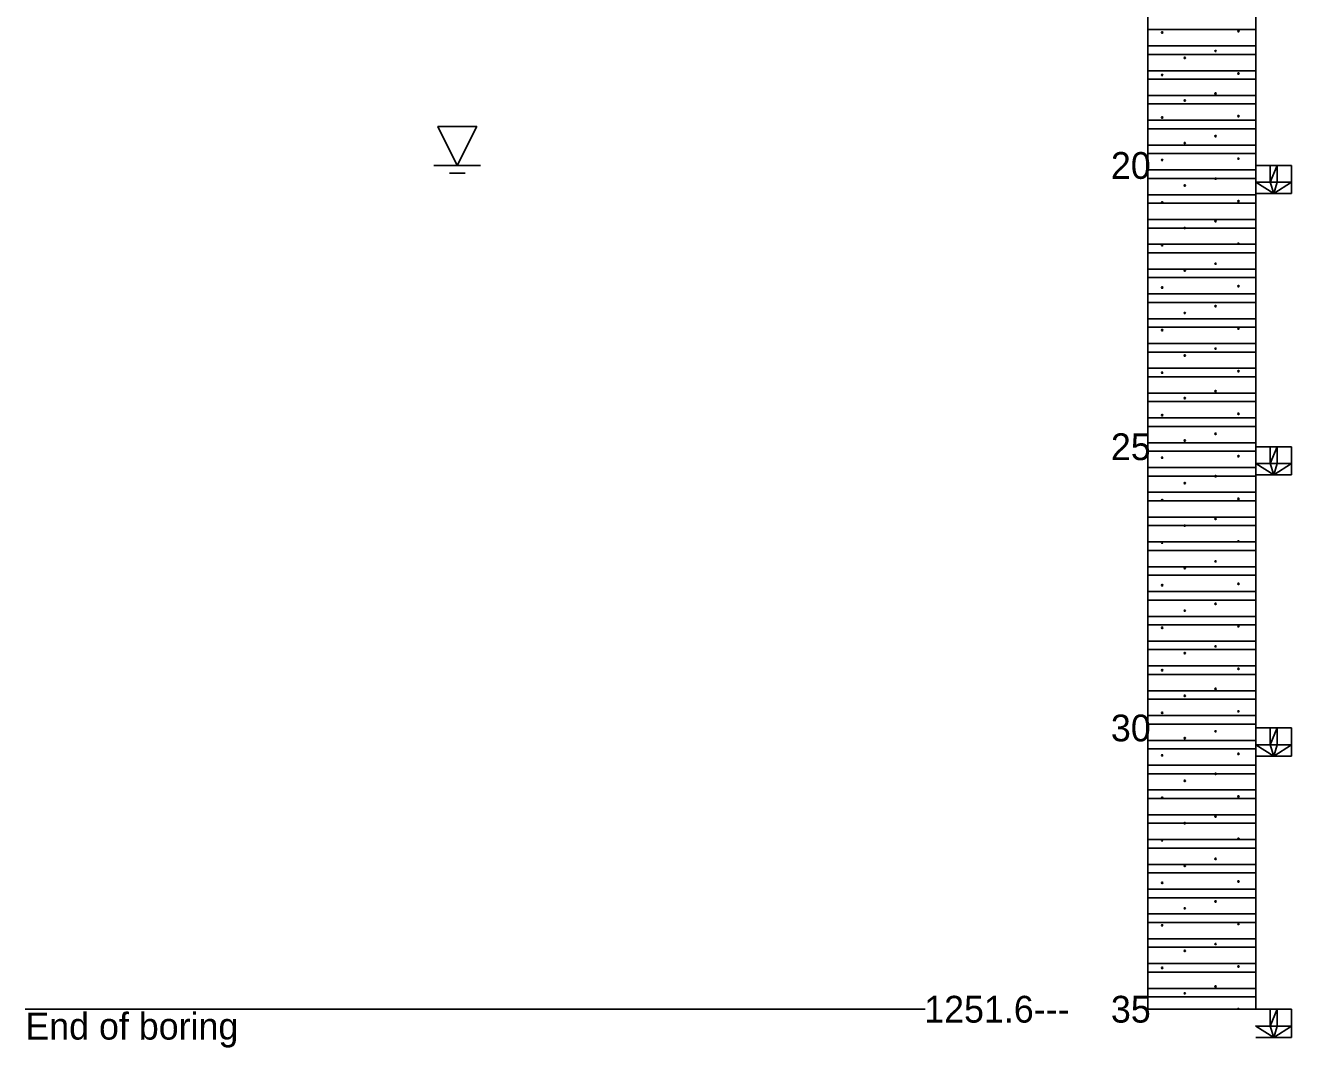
# Model space of a CAD drawing. Extents: x -2 to 138, y 24 to 58.
# Drawn here: x 54.71 to 60.57, y 39.72 to 44.45 of the extents above; entities that cross this region are included whole.
import ezdxf

# ---------------------------------------------------------------- set-up
doc = ezdxf.new("R2010")
doc.units = 0
doc.layers.add('Text', color=7, linetype='Continuous')

# ---------------------------------------------------------------- blocks, each defined once
blk = doc.blocks.new('DGRFC_WTLEV1_1')
for points in [[(0, 0), (0.00417, 0.00833), (-0.00417, 0.00833), (0, 0)], [(-0.005, 0), (0.005, 0)], [(-0.00167, -0.00167), (0.00167, -0.00167)]]:
    blk.add_lwpolyline(points)

msp = doc.modelspace()

# ---------------------------------------------------------------- linework, layer by layer
for points in [[(59.9039, 49.0098), (59.9039, 39.8952)], [(60.4039, 49.0098), (60.4039, 39.8952)], [(59.9039, 44.4306), (60.4039, 44.4306)], [(59.9743, 44.4172), (59.9726, 44.42), (59.9693, 44.42), (59.9677, 44.4172), (59.9693, 44.4143), (59.9726, 44.4143), (59.9743, 44.4172)], [(60.327, 44.4237), (60.3254, 44.4266), (60.3221, 44.4266), (60.3205, 44.4237), (60.3221, 44.4209), (60.3254, 44.4209), (60.327, 44.4237)], [(59.9039, 44.3551), (60.4039, 44.3551)], [(60.2215, 44.3312), (60.2199, 44.334), (60.2166, 44.334), (60.215, 44.3312), (60.2166, 44.3284), (60.2199, 44.3284), (60.2215, 44.3312)], [(59.9039, 44.3158), (60.4039, 44.3158)], [(60.0789, 44.2993), (60.0773, 44.3022), (60.074, 44.3022), (60.0724, 44.2993), (60.074, 44.2965), (60.0773, 44.2965), (60.0789, 44.2993)], [(59.9039, 44.2403), (60.4039, 44.2403)], [(59.9743, 44.2203), (59.9726, 44.2232), (59.9693, 44.2232), (59.9677, 44.2203), (59.9693, 44.2175), (59.9726, 44.2175), (59.9743, 44.2203)], [(60.327, 44.2268), (60.3254, 44.2297), (60.3221, 44.2297), (60.3205, 44.2268), (60.3221, 44.224), (60.3254, 44.224), (60.327, 44.2268)], [(59.9039, 44.2009), (60.4039, 44.2009)], [(59.9039, 44.1255), (60.4039, 44.1255)], [(60.0789, 44.1024), (60.0773, 44.1053), (60.074, 44.1053), (60.0724, 44.1025), (60.074, 44.0996), (60.0773, 44.0996), (60.0789, 44.1024)], [(60.2215, 44.1343), (60.2199, 44.1371), (60.2166, 44.1371), (60.215, 44.1343), (60.2166, 44.1315), (60.2199, 44.1315), (60.2215, 44.1343)], [(59.9039, 44.0861), (60.4039, 44.0861)], [(60.327, 44.03), (60.3254, 44.0329), (60.3221, 44.0329), (60.3205, 44.03), (60.3221, 44.0272), (60.3254, 44.0272), (60.327, 44.03)], [(59.9039, 44.0106), (60.4039, 44.0106)], [(59.9743, 44.0235), (59.9726, 44.0263), (59.9693, 44.0263), (59.9677, 44.0235), (59.9693, 44.0206), (59.9726, 44.0206), (59.9743, 44.0235)], [(59.9039, 43.9713), (60.4039, 43.9713)], [(60.2215, 43.9375), (60.2199, 43.9403), (60.2166, 43.9403), (60.215, 43.9375), (60.2166, 43.9347), (60.2199, 43.9347), (60.2215, 43.9375)], [(59.9039, 43.8958), (60.4039, 43.8958)], [(60.0789, 43.9056), (60.0773, 43.9085), (60.074, 43.9085), (60.0724, 43.9056), (60.074, 43.9028), (60.0773, 43.9028), (60.0789, 43.9056)], [(59.9039, 43.8564), (60.4039, 43.8564)], [(59.9743, 43.8266), (59.9726, 43.8295), (59.9693, 43.8295), (59.9677, 43.8266), (59.9693, 43.8238), (59.9726, 43.8238), (59.9743, 43.8266)], [(60.327, 43.8331), (60.3254, 43.836), (60.3221, 43.836), (60.3205, 43.8331), (60.3221, 43.8303), (60.3254, 43.8303), (60.327, 43.8331)], [(60.4039, 43.8015), (60.5705, 43.8015)], [(60.5705, 43.6713), (60.5705, 43.8015)], [(59.9039, 43.781), (60.4039, 43.781)], [(59.9039, 43.7416), (60.4039, 43.7416)], [(60.2215, 43.7406), (60.2199, 43.7434), (60.2166, 43.7434), (60.215, 43.7406), (60.2166, 43.7378), (60.2199, 43.7378), (60.2215, 43.7406)], [(60.0789, 43.7087), (60.0773, 43.7116), (60.074, 43.7116), (60.0724, 43.7088), (60.074, 43.7059), (60.0773, 43.7059), (60.0789, 43.7087)], [(59.9039, 43.6661), (60.4039, 43.6661)], [(59.9039, 43.6268), (60.4039, 43.6268)], [(59.9743, 43.6298), (59.9726, 43.6326), (59.9693, 43.6326), (59.9677, 43.6298), (59.9693, 43.6269), (59.9726, 43.6269), (59.9743, 43.6298)], [(60.327, 43.6363), (60.3254, 43.6392), (60.3221, 43.6392), (60.3205, 43.6363), (60.3221, 43.6335), (60.3254, 43.6335), (60.327, 43.6363)], [(60.4039, 43.6713), (60.5705, 43.6713)], [(59.9039, 43.5513), (60.4039, 43.5513)], [(59.9039, 43.5119), (60.4039, 43.5119)], [(60.0789, 43.5119), (60.0773, 43.5148), (60.074, 43.5148), (60.0724, 43.5119), (60.074, 43.5091), (60.0773, 43.5091), (60.0789, 43.5119)], [(60.2215, 43.5438), (60.2199, 43.5466), (60.2166, 43.5466), (60.215, 43.5438), (60.2166, 43.541), (60.2199, 43.541), (60.2215, 43.5438)], [(59.9039, 43.4365), (60.4039, 43.4365)], [(59.9039, 43.3971), (60.4039, 43.3971)], [(59.9743, 43.4329), (59.9726, 43.4358), (59.9693, 43.4358), (59.9677, 43.4329), (59.9693, 43.4301), (59.9726, 43.4301), (59.9743, 43.4329)], [(60.327, 43.4394), (60.3254, 43.4423), (60.3221, 43.4423), (60.3205, 43.4394), (60.3221, 43.4366), (60.3254, 43.4366), (60.327, 43.4394)], [(60.2215, 43.3469), (60.2199, 43.3497), (60.2166, 43.3497), (60.215, 43.3469), (60.2166, 43.3441), (60.2199, 43.3441), (60.2215, 43.3469)], [(59.9039, 43.3217), (60.4039, 43.3217)], [(59.9039, 43.2823), (60.4039, 43.2823)], [(60.0789, 43.315), (60.0773, 43.3179), (60.074, 43.3179), (60.0724, 43.3151), (60.074, 43.3122), (60.0773, 43.3122), (60.0789, 43.315)], [(59.9743, 43.2361), (59.9726, 43.2389), (59.9693, 43.2389), (59.9677, 43.2361), (59.9693, 43.2332), (59.9726, 43.2332), (59.9743, 43.2361)], [(60.327, 43.2426), (60.3254, 43.2455), (60.3221, 43.2455), (60.3205, 43.2426), (60.3221, 43.2398), (60.3254, 43.2398), (60.327, 43.2426)], [(59.9039, 43.2068), (60.4039, 43.2068)], [(59.9039, 43.1675), (60.4039, 43.1675)], [(60.0789, 43.1182), (60.0773, 43.1211), (60.074, 43.1211), (60.0724, 43.1182), (60.074, 43.1154), (60.0773, 43.1154), (60.0789, 43.1182)], [(60.2215, 43.1501), (60.2199, 43.1529), (60.2166, 43.1529), (60.215, 43.1501), (60.2166, 43.1472), (60.2199, 43.1472), (60.2215, 43.1501)], [(59.9039, 43.092), (60.4039, 43.092)], [(59.9039, 43.0526), (60.4039, 43.0526)], [(59.9743, 43.0392), (59.9726, 43.0421), (59.9693, 43.0421), (59.9677, 43.0392), (59.9693, 43.0364), (59.9726, 43.0364), (59.9743, 43.0392)], [(60.327, 43.0457), (60.3254, 43.0486), (60.3221, 43.0486), (60.3205, 43.0457), (60.3221, 43.0429), (60.3254, 43.0429), (60.327, 43.0457)], [(59.9039, 42.9772), (60.4039, 42.9772)], [(59.9039, 42.9378), (60.4039, 42.9378)], [(60.0789, 42.9213), (60.0773, 42.9242), (60.074, 42.9242), (60.0724, 42.9214), (60.074, 42.9185), (60.0773, 42.9185), (60.0789, 42.9213)], [(60.2215, 42.9532), (60.2199, 42.956), (60.2166, 42.956), (60.215, 42.9532), (60.2166, 42.9504), (60.2199, 42.9504), (60.2215, 42.9532)], [(59.9039, 42.8623), (60.4039, 42.8623)], [(59.9039, 42.823), (60.4039, 42.823)], [(59.9743, 42.8424), (59.9726, 42.8452), (59.9693, 42.8452), (59.9677, 42.8424), (59.9693, 42.8395), (59.9726, 42.8395), (59.9743, 42.8424)], [(60.327, 42.8489), (60.3254, 42.8518), (60.3221, 42.8518), (60.3205, 42.8489), (60.3221, 42.8461), (60.3254, 42.8461), (60.327, 42.8489)], [(59.9039, 42.7475), (60.4039, 42.7475)], [(60.2215, 42.7564), (60.2199, 42.7592), (60.2166, 42.7592), (60.215, 42.7564), (60.2166, 42.7535), (60.2199, 42.7535), (60.2215, 42.7564)], [(59.9039, 42.7081), (60.4039, 42.7081)], [(60.0789, 42.7245), (60.0773, 42.7274), (60.074, 42.7274), (60.0724, 42.7245), (60.074, 42.7217), (60.0773, 42.7217), (60.0789, 42.7245)], [(59.9039, 42.6327), (60.4039, 42.6327)], [(59.9743, 42.6455), (59.9726, 42.6484), (59.9693, 42.6484), (59.9677, 42.6455), (59.9693, 42.6427), (59.9726, 42.6427), (59.9743, 42.6455)], [(60.327, 42.652), (60.3254, 42.6549), (60.3221, 42.6549), (60.3205, 42.652), (60.3221, 42.6492), (60.3254, 42.6492), (60.327, 42.652)], [(59.9039, 42.5933), (60.4039, 42.5933)], [(59.9039, 42.5179), (60.4039, 42.5179)], [(60.0789, 42.5276), (60.0773, 42.5305), (60.074, 42.5305), (60.0724, 42.5277), (60.074, 42.5248), (60.0773, 42.5248), (60.0789, 42.5276)], [(60.2215, 42.5595), (60.2199, 42.5623), (60.2166, 42.5623), (60.215, 42.5595), (60.2166, 42.5567), (60.2199, 42.5567), (60.2215, 42.5595)], [(59.9039, 42.4785), (60.4039, 42.4785)], [(59.9743, 42.4487), (59.9726, 42.4515), (59.9693, 42.4515), (59.9677, 42.4487), (59.9693, 42.4458), (59.9726, 42.4458), (59.9743, 42.4487)], [(60.327, 42.4552), (60.3254, 42.4581), (60.3221, 42.4581), (60.3205, 42.4552), (60.3221, 42.4524), (60.3254, 42.4524), (60.327, 42.4552)], [(60.4039, 42.4994), (60.5705, 42.4994)], [(60.5705, 42.3692), (60.5705, 42.4994)], [(59.9039, 42.403), (60.4039, 42.403)], [(59.9039, 42.3637), (60.4039, 42.3637)], [(60.0789, 42.3308), (60.0773, 42.3337), (60.074, 42.3337), (60.0724, 42.3308), (60.074, 42.328), (60.0773, 42.328), (60.0789, 42.3308)], [(60.2215, 42.3627), (60.2199, 42.3655), (60.2166, 42.3655), (60.215, 42.3627), (60.2166, 42.3598), (60.2199, 42.3598), (60.2215, 42.3627)], [(60.4039, 42.3692), (60.5705, 42.3692)], [(59.9039, 42.2882), (60.4039, 42.2882)], [(59.9039, 42.2488), (60.4039, 42.2488)], [(59.9743, 42.2518), (59.9726, 42.2547), (59.9693, 42.2547), (59.9677, 42.2518), (59.9693, 42.249), (59.9726, 42.249), (59.9743, 42.2518)], [(60.327, 42.2583), (60.3254, 42.2612), (60.3221, 42.2612), (60.3205, 42.2583), (60.3221, 42.2555), (60.3254, 42.2555), (60.327, 42.2583)], [(59.9039, 42.1734), (60.4039, 42.1734)], [(60.2215, 42.1658), (60.2199, 42.1686), (60.2166, 42.1686), (60.215, 42.1658), (60.2166, 42.163), (60.2199, 42.163), (60.2215, 42.1658)], [(59.9039, 42.134), (60.4039, 42.134)], [(60.0789, 42.1339), (60.0773, 42.1368), (60.074, 42.1368), (60.0724, 42.134), (60.074, 42.1311), (60.0773, 42.1311), (60.0789, 42.1339)], [(59.9039, 42.0585), (60.4039, 42.0585)], [(59.9743, 42.055), (59.9726, 42.0578), (59.9693, 42.0578), (59.9677, 42.055), (59.9693, 42.0521), (59.9726, 42.0521), (59.9743, 42.055)], [(60.327, 42.0615), (60.3254, 42.0644), (60.3221, 42.0644), (60.3205, 42.0615), (60.3221, 42.0587), (60.3254, 42.0587), (60.327, 42.0615)], [(59.9039, 42.0192), (60.4039, 42.0192)], [(59.9039, 41.9437), (60.4039, 41.9437)], [(60.0789, 41.9371), (60.0773, 41.94), (60.074, 41.94), (60.0724, 41.9371), (60.074, 41.9343), (60.0773, 41.9343), (60.0789, 41.9371)], [(60.2215, 41.969), (60.2199, 41.9718), (60.2166, 41.9718), (60.215, 41.969), (60.2166, 41.9661), (60.2199, 41.9661), (60.2215, 41.969)], [(59.9039, 41.9043), (60.4039, 41.9043)], [(60.327, 41.8646), (60.3254, 41.8675), (60.3221, 41.8675), (60.3205, 41.8646), (60.3221, 41.8618), (60.3254, 41.8618), (60.327, 41.8646)], [(59.9039, 41.8289), (60.4039, 41.8289)], [(59.9743, 41.8581), (59.9726, 41.861), (59.9693, 41.861), (59.9677, 41.8581), (59.9693, 41.8553), (59.9726, 41.8553), (59.9743, 41.8581)], [(59.9039, 41.7895), (60.4039, 41.7895)], [(60.2215, 41.7721), (60.2199, 41.7749), (60.2166, 41.7749), (60.215, 41.7721), (60.2166, 41.7693), (60.2199, 41.7693), (60.2215, 41.7721)], [(59.9039, 41.714), (60.4039, 41.714)], [(60.0789, 41.7402), (60.0773, 41.7431), (60.074, 41.7431), (60.0724, 41.7403), (60.074, 41.7374), (60.0773, 41.7374), (60.0789, 41.7402)], [(59.9039, 41.6747), (60.4039, 41.6747)], [(59.9743, 41.6613), (59.9726, 41.6641), (59.9693, 41.6641), (59.9677, 41.6613), (59.9693, 41.6584), (59.9726, 41.6584), (59.9743, 41.6613)], [(60.327, 41.6678), (60.3254, 41.6707), (60.3221, 41.6707), (60.3205, 41.6678), (60.3221, 41.665), (60.3254, 41.665), (60.327, 41.6678)], [(59.9039, 41.5992), (60.4039, 41.5992)], [(60.2215, 41.5753), (60.2199, 41.5781), (60.2166, 41.5781), (60.215, 41.5753), (60.2166, 41.5724), (60.2199, 41.5724), (60.2215, 41.5753)], [(59.9039, 41.5598), (60.4039, 41.5598)], [(60.0789, 41.5434), (60.0773, 41.5463), (60.074, 41.5463), (60.0724, 41.5434), (60.074, 41.5406), (60.0773, 41.5406), (60.0789, 41.5434)], [(59.9039, 41.4844), (60.4039, 41.4844)], [(59.9743, 41.4644), (59.9726, 41.4673), (59.9693, 41.4673), (59.9677, 41.4644), (59.9693, 41.4616), (59.9726, 41.4616), (59.9743, 41.4644)], [(60.327, 41.4709), (60.3254, 41.4738), (60.3221, 41.4738), (60.3205, 41.4709), (60.3221, 41.4681), (60.3254, 41.4681), (60.327, 41.4709)], [(59.9039, 41.445), (60.4039, 41.445)], [(59.9039, 41.3696), (60.4039, 41.3696)], [(60.0789, 41.3465), (60.0773, 41.3494), (60.074, 41.3494), (60.0724, 41.3466), (60.074, 41.3437), (60.0773, 41.3437), (60.0789, 41.3465)], [(60.2215, 41.3784), (60.2199, 41.3812), (60.2166, 41.3812), (60.215, 41.3784), (60.2166, 41.3756), (60.2199, 41.3756), (60.2215, 41.3784)], [(59.9039, 41.3302), (60.4039, 41.3302)], [(59.9039, 41.2547), (60.4039, 41.2547)], [(59.9743, 41.2676), (59.9726, 41.2704), (59.9693, 41.2704), (59.9677, 41.2676), (59.9693, 41.2647), (59.9726, 41.2647), (59.9743, 41.2676)], [(60.327, 41.2741), (60.3254, 41.277), (60.3221, 41.277), (60.3205, 41.2741), (60.3221, 41.2713), (60.3254, 41.2713), (60.327, 41.2741)], [(59.9039, 41.2154), (60.4039, 41.2154)], [(60.2215, 41.1816), (60.2199, 41.1844), (60.2166, 41.1844), (60.215, 41.1816), (60.2166, 41.1787), (60.2199, 41.1787), (60.2215, 41.1816)], [(60.4039, 41.1973), (60.5705, 41.1973)], [(60.5705, 41.0671), (60.5705, 41.1973)], [(59.9039, 41.1399), (60.4039, 41.1399)], [(60.0789, 41.1497), (60.0773, 41.1526), (60.074, 41.1526), (60.0724, 41.1497), (60.074, 41.1469), (60.0773, 41.1469), (60.0789, 41.1497)], [(59.9039, 41.1005), (60.4039, 41.1005)], [(59.9743, 41.0707), (59.9726, 41.0736), (59.9693, 41.0736), (59.9677, 41.0707), (59.9693, 41.0679), (59.9726, 41.0679), (59.9743, 41.0707)], [(60.327, 41.0772), (60.3254, 41.0801), (60.3221, 41.0801), (60.3205, 41.0772), (60.3221, 41.0744), (60.3254, 41.0744), (60.327, 41.0772)], [(60.4039, 41.0671), (60.5705, 41.0671)], [(59.9039, 41.0251), (60.4039, 41.0251)], [(59.9039, 40.9857), (60.4039, 40.9857)], [(60.2215, 40.9847), (60.2199, 40.9875), (60.2166, 40.9875), (60.215, 40.9847), (60.2166, 40.9819), (60.2199, 40.9819), (60.2215, 40.9847)], [(60.0789, 40.9528), (60.0773, 40.9557), (60.074, 40.9557), (60.0724, 40.9529), (60.074, 40.95), (60.0773, 40.95), (60.0789, 40.9528)], [(59.9039, 40.9102), (60.4039, 40.9102)], [(59.9039, 40.8709), (60.4039, 40.8709)], [(59.9743, 40.8739), (59.9726, 40.8767), (59.9693, 40.8767), (59.9677, 40.8739), (59.9693, 40.871), (59.9726, 40.871), (59.9743, 40.8739)], [(60.327, 40.8804), (60.3254, 40.8833), (60.3221, 40.8833), (60.3205, 40.8804), (60.3221, 40.8776), (60.3254, 40.8776), (60.327, 40.8804)], [(59.9039, 40.7954), (60.4039, 40.7954)], [(59.9039, 40.756), (60.4039, 40.756)], [(60.0789, 40.756), (60.0773, 40.7589), (60.074, 40.7589), (60.0724, 40.756), (60.074, 40.7532), (60.0773, 40.7532), (60.0789, 40.756)], [(60.2215, 40.7879), (60.2199, 40.7907), (60.2166, 40.7907), (60.215, 40.7879), (60.2166, 40.785), (60.2199, 40.785), (60.2215, 40.7879)], [(59.9039, 40.6806), (60.4039, 40.6806)], [(59.9039, 40.6412), (60.4039, 40.6412)], [(59.9743, 40.677), (59.9726, 40.6799), (59.9693, 40.6799), (59.9677, 40.677), (59.9693, 40.6742), (59.9726, 40.6742), (59.9743, 40.677)], [(60.327, 40.6835), (60.3254, 40.6864), (60.3221, 40.6864), (60.3205, 40.6835), (60.3221, 40.6807), (60.3254, 40.6807), (60.327, 40.6835)], [(60.2215, 40.591), (60.2199, 40.5938), (60.2166, 40.5938), (60.215, 40.591), (60.2166, 40.5882), (60.2199, 40.5882), (60.2215, 40.591)], [(59.9039, 40.5658), (60.4039, 40.5658)], [(59.9039, 40.5264), (60.4039, 40.5264)], [(60.0789, 40.5591), (60.0773, 40.562), (60.074, 40.562), (60.0724, 40.5592), (60.074, 40.5563), (60.0773, 40.5563), (60.0789, 40.5591)], [(59.9743, 40.4802), (59.9726, 40.483), (59.9693, 40.483), (59.9677, 40.4802), (59.9693, 40.4773), (59.9726, 40.4773), (59.9743, 40.4802)], [(60.327, 40.4867), (60.3254, 40.4896), (60.3221, 40.4896), (60.3205, 40.4867), (60.3221, 40.4839), (60.3254, 40.4839), (60.327, 40.4867)], [(59.9039, 40.4509), (60.4039, 40.4509)], [(59.9039, 40.4116), (60.4039, 40.4116)], [(60.0789, 40.3623), (60.0773, 40.3652), (60.074, 40.3652), (60.0724, 40.3623), (60.074, 40.3595), (60.0773, 40.3595), (60.0789, 40.3623)], [(60.2215, 40.3942), (60.2199, 40.397), (60.2166, 40.397), (60.215, 40.3942), (60.2166, 40.3913), (60.2199, 40.3913), (60.2215, 40.3942)], [(59.9039, 40.3361), (60.4039, 40.3361)], [(59.9039, 40.2967), (60.4039, 40.2967)], [(59.9743, 40.2833), (59.9726, 40.2862), (59.9693, 40.2862), (59.9677, 40.2833), (59.9693, 40.2805), (59.9726, 40.2805), (59.9743, 40.2833)], [(60.327, 40.2898), (60.3254, 40.2927), (60.3221, 40.2927), (60.3205, 40.2898), (60.3221, 40.287), (60.3254, 40.287), (60.327, 40.2898)], [(59.9039, 40.2213), (60.4039, 40.2213)], [(59.9039, 40.1819), (60.4039, 40.1819)], [(60.0789, 40.1654), (60.0773, 40.1683), (60.074, 40.1683), (60.0724, 40.1655), (60.074, 40.1626), (60.0773, 40.1626), (60.0789, 40.1654)], [(60.2215, 40.1973), (60.2199, 40.2001), (60.2166, 40.2001), (60.215, 40.1973), (60.2166, 40.1945), (60.2199, 40.1945), (60.2215, 40.1973)], [(59.9039, 40.1064), (60.4039, 40.1064)], [(59.9039, 40.0671), (60.4039, 40.0671)], [(59.9743, 40.0865), (59.9726, 40.0893), (59.9693, 40.0893), (59.9677, 40.0865), (59.9693, 40.0836), (59.9726, 40.0836), (59.9743, 40.0865)], [(60.327, 40.093), (60.3254, 40.0959), (60.3221, 40.0959), (60.3205, 40.093), (60.3221, 40.0902), (60.3254, 40.0902), (60.327, 40.093)], [(59.9039, 39.9916), (60.4039, 39.9916)], [(60.2215, 40.0005), (60.2199, 40.0033), (60.2166, 40.0033), (60.215, 40.0005), (60.2166, 39.9976), (60.2199, 39.9976), (60.2215, 40.0005)], [(59.9039, 39.9522), (60.4039, 39.9522)], [(60.0789, 39.9686), (60.0773, 39.9715), (60.074, 39.9715), (60.0724, 39.9686), (60.074, 39.9658), (60.0773, 39.9658), (60.0789, 39.9686)], [(54.7073, 39.8952), (58.874, 39.8952)], [(59.9039, 39.8952), (60.4039, 39.8952)], [(60.327, 39.8961), (60.3254, 39.899), (60.3221, 39.899), (60.3205, 39.8961), (60.321, 39.8952), (60.3265, 39.8952), (60.327, 39.8961)], [(60.4039, 39.8952), (60.5705, 39.8952)], [(60.5705, 39.765), (60.5705, 39.8952)], [(60.4039, 39.765), (60.5705, 39.765)]]:
    msp.add_lwpolyline(points)
for points in [[(60.4705, 43.7234), (60.5039, 43.7234), (60.5039, 43.8015), (60.4705, 43.7234)], [(60.4705, 43.7234), (60.5039, 43.8015), (60.4705, 43.8015), (60.4705, 43.7234)], [(60.4705, 43.7234), (60.4039, 43.7234), (60.4872, 43.6713), (60.4705, 43.7234)], [(60.4705, 43.7234), (60.4872, 43.6713), (60.5039, 43.7234), (60.4705, 43.7234)], [(60.4872, 43.6713), (60.5705, 43.7234), (60.5039, 43.7234), (60.4872, 43.6713)], [(60.4705, 42.4213), (60.5039, 42.4213), (60.5039, 42.4994), (60.4705, 42.4213)], [(60.4705, 42.4213), (60.5039, 42.4994), (60.4705, 42.4994), (60.4705, 42.4213)], [(60.4705, 42.4213), (60.4039, 42.4213), (60.4872, 42.3692), (60.4705, 42.4213)], [(60.4705, 42.4213), (60.4872, 42.3692), (60.5039, 42.4213), (60.4705, 42.4213)], [(60.4872, 42.3692), (60.5705, 42.4213), (60.5039, 42.4213), (60.4872, 42.3692)], [(60.4705, 41.1192), (60.5039, 41.1192), (60.5039, 41.1973), (60.4705, 41.1192)], [(60.4705, 41.1192), (60.5039, 41.1973), (60.4705, 41.1973), (60.4705, 41.1192)], [(60.4705, 41.1192), (60.4039, 41.1192), (60.4872, 41.0671), (60.4705, 41.1192)], [(60.4705, 41.1192), (60.4872, 41.0671), (60.5039, 41.1192), (60.4705, 41.1192)], [(60.4872, 41.0671), (60.5705, 41.1192), (60.5039, 41.1192), (60.4872, 41.0671)], [(60.4705, 39.8171), (60.5039, 39.8171), (60.5039, 39.8952), (60.4705, 39.8171)], [(60.4705, 39.8171), (60.5039, 39.8952), (60.4705, 39.8952), (60.4705, 39.8171)], [(60.4705, 39.8171), (60.4039, 39.8171), (60.4872, 39.765), (60.4705, 39.8171)], [(60.4705, 39.8171), (60.4872, 39.765), (60.5039, 39.8171), (60.4705, 39.8171)], [(60.4872, 39.765), (60.5705, 39.8171), (60.5039, 39.8171), (60.4872, 39.765)]]:
    msp.add_lwpolyline(points, close=True)

# ---------------------------------------------------------------- block references
at = {"layer": 'Text', "xscale": 21.6, "yscale": 21.6}
msp.add_blockref('DGRFC_WTLEV1_1', (56.7073, 43.8015), dxfattribs=at)

# ---------------------------------------------------------------- texts
for s, p in [('20', (59.7335, 43.7395)), ('25', (59.7335, 42.4374)), ('30', (59.7335, 41.1353)), ('1251.6---', (58.8691, 39.8332)), ('35', (59.7335, 39.8332)), ('End of boring', (54.7073, 39.7546))]:
    msp.add_text(s, height=0.124).set_placement(p)

doc.saveas('drawing.dxf')
